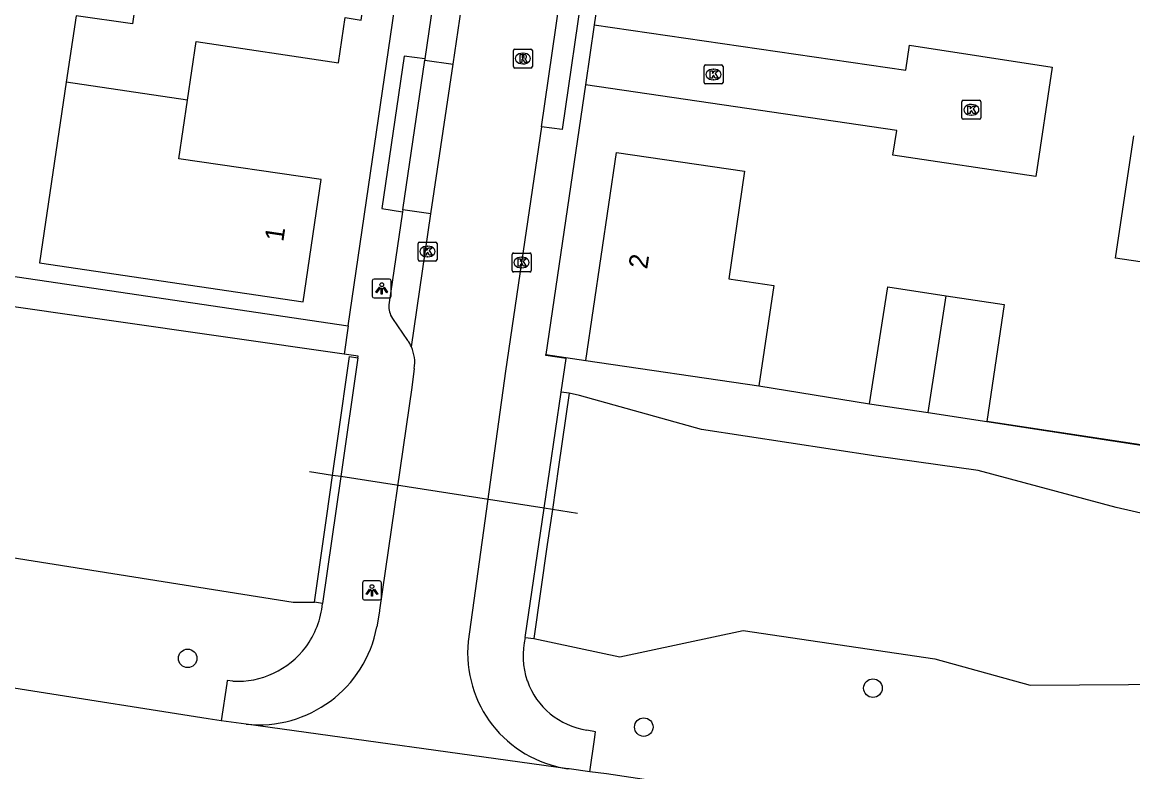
# Model space of a CAD drawing. Extents: x 164150 to 165261, y 382513 to 383432.
# Drawn here: x 164510.6 to 164569.1, y 382845.8 to 382885.3 of the extents above; entities that cross this region are included whole.
import ezdxf

# ---------------------------------------------------------------- set-up
doc = ezdxf.new("R2010")
doc.units = 0
for name, color, linetype in [('IMGEO_Boom', 7, 'Continuous'), ('IMGEO_Duiker', 7, 'Continuous'), ('IMGEO_Greppel_droge_sloot', 7, 'Continuous'), ('IMGEO_Groenvoorziening', 7, 'Continuous'), ('IMGEO_Hek', 7, 'Continuous'), ('IMGEO_Kolk', 7, 'Continuous'), ('IMGEO_Lichtpunt', 7, 'Continuous'), ('IMGEO_Muur', 7, 'Continuous'), ('IMGEO_Pand', 7, 'Continuous'), ('IMGEO_Pand_nummerreeks', 7, 'Continuous'), ('IMGEO_Rijbaan_lokaal_gesloten', 7, 'Continuous'), ('IMGEO_Rijbaan_lokaal_open', 7, 'Continuous'), ('IMGEO_Rioolput', 7, 'Continuous'), ('IMGEO_Voetpad_open', 7, 'Continuous')]:
    doc.layers.add(name, color=color, linetype=linetype)

msp = doc.modelspace()

# ---------------------------------------------------------------- linework, layer by layer
at = {"layer": 'IMGEO_Boom'}
for centre in [(164519.276, 382851.814), (164555.378, 382850.247), (164543.305, 382848.195)]:
    msp.add_circle(centre, 0.489, dxfattribs=at)
at = {"layer": 'IMGEO_Duiker'}
msp.add_lwpolyline([(164539.809, 382859.446), (164538.49, 382859.651), (164538.061, 382859.718), (164527.339, 382861.387), (164526.913, 382861.453), (164525.694, 382861.643)], dxfattribs=at)
at = {"layer": 'IMGEO_Greppel_droge_sloot'}
for points in [[(164527.513, 382867.841), (164483.733, 382874.094), (164468.94, 382876.903), (164467.772, 382876.998)], [(164537.505, 382852.864), (164542.036, 382851.887), (164548.533, 382853.274), (164558.634, 382851.789), (164563.666, 382850.409), (164571.442, 382850.449), (164574.386, 382851.72), (164575.696, 382852.791), (164576.085, 382854.562), (164576.126, 382855.081), (164576.192, 382855.907), (164575.306, 382857.819), (164573.253, 382858.598), (164568.189, 382859.767), (164560.93, 382861.714), (164555.547, 382862.458), (164546.34, 382863.875), (164539.927, 382865.663), (164539.378, 382865.774)], [(164465.924, 382864.054), (164484.051, 382861.245), (164524.835, 382854.782), (164525.957, 382854.773)]]:
    msp.add_lwpolyline(points, dxfattribs=at)
at = {"layer": 'IMGEO_Groenvoorziening'}
for points in [[(164478.67, 382881.048), (164478.137, 382876.668), (164527.73, 382869.322)], [(164538.147, 382867.82), (164540.257, 382867.51)], [(164549.374, 382866.172), (164555.201, 382865.227)], [(164561.373, 382864.283), (164577.746, 382861.779)]]:
    msp.add_lwpolyline(points, dxfattribs=at)
at = {"layer": 'IMGEO_Hek'}
msp.add_lwpolyline([(164578.881, 382869.483), (164577.716, 382861.817), (164561.373, 382864.283)], dxfattribs=at)
at = {"layer": 'IMGEO_Kolk'}
for p, q in [((164546.479, 382882.139), (164546.479, 382882.991)), ((164546.554, 382883.065), (164547.406, 382883.065)), ((164546.967, 382882.845), (164546.992, 382882.845)), ((164547.48, 382882.991), (164547.48, 382882.139)), ((164546.99, 382882.285), (164546.965, 382882.285)), ((164547.406, 382882.065), (164546.554, 382882.065)), ((164560.064, 382880.279), (164560.064, 382881.131)), ((164560.139, 382881.205), (164560.991, 382881.205)), ((164561.065, 382881.131), (164561.065, 382880.279)), ((164560.552, 382880.985), (164560.577, 382880.985)), ((164560.991, 382880.205), (164560.139, 382880.205)), ((164560.575, 382880.425), (164560.55, 382880.425)), ((164531.413, 382872.815), (164531.413, 382873.667)), ((164531.488, 382873.741), (164532.34, 382873.741)), ((164531.901, 382873.521), (164531.926, 382873.521)), ((164532.414, 382873.667), (164532.414, 382872.815)), ((164531.924, 382872.961), (164531.899, 382872.961)), ((164536.367, 382872.237), (164536.367, 382873.089)), ((164536.442, 382873.163), (164537.294, 382873.163)), ((164536.855, 382872.943), (164536.88, 382872.943)), ((164537.368, 382873.089), (164537.368, 382872.237)), ((164532.34, 382872.741), (164531.488, 382872.741)), ((164536.878, 382872.383), (164536.853, 382872.383)), ((164537.294, 382872.163), (164536.442, 382872.163))]:
    msp.add_line(p, q, dxfattribs=at)
for points in [[(164546.479, 382882.139), (164546.479, 382882.991)], [(164546.554, 382883.065), (164547.406, 382883.065)], [(164547.48, 382882.991), (164547.48, 382882.139)], [(164546.8, 382882.765), (164546.923, 382882.765), (164546.923, 382882.614), (164547.053, 382882.765), (164547.217, 382882.765), (164547.071, 382882.614), (164547.224, 382882.365), (164547.072, 382882.365), (164546.987, 382882.529), (164546.923, 382882.462), (164546.923, 382882.365), (164546.8, 382882.365), (164546.8, 382882.765)], [(164547.406, 382882.065), (164546.554, 382882.065)], [(164560.064, 382880.279), (164560.064, 382881.131)], [(164560.139, 382881.205), (164560.991, 382881.205)], [(164561.065, 382881.131), (164561.065, 382880.279)], [(164560.385, 382880.905), (164560.508, 382880.905), (164560.508, 382880.754), (164560.638, 382880.905), (164560.802, 382880.905), (164560.656, 382880.754), (164560.809, 382880.505), (164560.657, 382880.505), (164560.572, 382880.669), (164560.508, 382880.602), (164560.508, 382880.505), (164560.385, 382880.505), (164560.385, 382880.905)], [(164560.991, 382880.205), (164560.139, 382880.205)], [(164531.413, 382872.815), (164531.413, 382873.667)], [(164531.488, 382873.741), (164532.34, 382873.741)], [(164532.414, 382873.667), (164532.414, 382872.815)], [(164531.734, 382873.441), (164531.857, 382873.441), (164531.857, 382873.29), (164531.987, 382873.441), (164532.151, 382873.441), (164532.005, 382873.29), (164532.158, 382873.041), (164532.006, 382873.041), (164531.921, 382873.205), (164531.857, 382873.138), (164531.857, 382873.041), (164531.734, 382873.041), (164531.734, 382873.441)], [(164536.367, 382872.237), (164536.367, 382873.089)], [(164536.442, 382873.163), (164537.294, 382873.163)], [(164537.368, 382873.089), (164537.368, 382872.237)], [(164532.34, 382872.741), (164531.488, 382872.741)], [(164536.688, 382872.863), (164536.811, 382872.863), (164536.811, 382872.712), (164536.941, 382872.863), (164537.105, 382872.863), (164536.959, 382872.712), (164537.112, 382872.463), (164536.96, 382872.463), (164536.875, 382872.627), (164536.811, 382872.56), (164536.811, 382872.463), (164536.688, 382872.463), (164536.688, 382872.863)], [(164537.294, 382872.163), (164536.442, 382872.163)]]:
    msp.add_lwpolyline(points, dxfattribs=at)
for centre, start, end in [((164546.556, 382882.989), 91.55205, 178.44795), ((164546.556, 382882.989), 91.55205, 178.44795), ((164547.404, 382882.989), 1.55205, 88.44795), ((164547.404, 382882.989), 1.55205, 88.44795), ((164546.556, 382882.141), 181.55205, 268.44795), ((164546.556, 382882.141), 181.55205, 268.44795), ((164547.404, 382882.141), 271.55205, 358.44795), ((164547.404, 382882.141), 271.55205, 358.44795), ((164560.141, 382881.129), 91.55205, 178.44795), ((164560.141, 382881.129), 91.55205, 178.44795), ((164560.989, 382881.129), 1.55205, 88.44795), ((164560.989, 382881.129), 1.55205, 88.44795), ((164560.141, 382880.281), 181.55205, 268.44795), ((164560.141, 382880.281), 181.55205, 268.44795), ((164560.989, 382880.281), 271.55205, 358.44795), ((164560.989, 382880.281), 271.55205, 358.44795), ((164531.49, 382873.665), 91.55205, 178.44795), ((164531.49, 382873.665), 91.55205, 178.44795), ((164532.338, 382873.665), 1.55205, 88.44795), ((164532.338, 382873.665), 1.55205, 88.44795), ((164536.444, 382873.087), 91.55205, 178.44795), ((164536.444, 382873.087), 91.55205, 178.44795), ((164537.292, 382873.087), 1.55205, 88.44795), ((164537.292, 382873.087), 1.55205, 88.44795), ((164531.49, 382872.817), 181.55205, 268.44795), ((164531.49, 382872.817), 181.55205, 268.44795), ((164532.338, 382872.817), 271.55205, 358.44795), ((164532.338, 382872.817), 271.55205, 358.44795), ((164536.444, 382872.239), 181.55205, 268.44795), ((164536.444, 382872.239), 181.55205, 268.44795), ((164537.292, 382872.239), 271.55205, 358.44795), ((164537.292, 382872.239), 271.55205, 358.44795)]:
    msp.add_arc(centre, 0.0765, start, end, dxfattribs=at)
for centre, major_axis, ratio, start_param, end_param in [((164546.966, 382882.565), (-0.387, 0.002), 0.722429, 4.712389, 7.853982), ((164546.991, 382882.565), (-0.39, 0.002), 0.717154, 1.570796, 4.712389), ((164560.551, 382880.705), (-0.387, 0.002), 0.722429, 4.712389, 7.853982), ((164560.576, 382880.705), (-0.39, 0.002), 0.717154, 1.570796, 4.712389), ((164531.9, 382873.241), (-0.387, 0.002), 0.722429, 4.712389, 7.853982), ((164531.925, 382873.241), (-0.39, 0.002), 0.717154, 1.570796, 4.712389), ((164536.854, 382872.663), (-0.387, 0.002), 0.722429, 4.712389, 7.853982), ((164536.879, 382872.663), (-0.39, 0.002), 0.717154, 1.570796, 4.712389)]:
    msp.add_ellipse(centre, major_axis=major_axis, ratio=ratio, start_param=start_param, end_param=end_param, dxfattribs=at)
at = {"layer": 'IMGEO_Lichtpunt'}
for p, q in [((164529.903, 382871.791), (164529.095, 382871.791)), ((164529.903, 382871.791), (164529.095, 382871.791)), ((164529.001, 382871.696), (164529.001, 382870.889)), ((164529.001, 382871.696), (164529.001, 382870.889)), ((164529.997, 382870.889), (164529.997, 382871.696)), ((164529.997, 382870.889), (164529.997, 382871.696)), ((164529.095, 382870.795), (164529.903, 382870.795)), ((164529.095, 382870.795), (164529.903, 382870.795)), ((164528.487, 382855.797), (164528.487, 382854.99)), ((164528.487, 382855.797), (164528.487, 382854.99)), ((164529.389, 382855.892), (164528.581, 382855.892)), ((164529.389, 382855.892), (164528.581, 382855.892)), ((164529.483, 382854.99), (164529.483, 382855.797)), ((164529.483, 382854.99), (164529.483, 382855.797)), ((164528.581, 382854.896), (164529.389, 382854.896)), ((164528.581, 382854.896), (164529.389, 382854.896))]:
    msp.add_line(p, q, dxfattribs=at)
for points in [[(164529.375, 382871.36), (164529.414, 382871.332), (164529.226, 382871.07), (164529.188, 382871.097), (164529.375, 382871.36)], [(164529.477, 382871.312), (164529.524, 382871.312), (164529.524, 382870.99), (164529.477, 382870.99), (164529.477, 382871.312)], [(164529.587, 382871.332), (164529.625, 382871.359), (164529.812, 382871.097), (164529.773, 382871.069), (164529.587, 382871.332)], [(164528.861, 382855.461), (164528.9, 382855.433), (164528.712, 382855.171), (164528.674, 382855.198), (164528.861, 382855.461)], [(164528.963, 382855.413), (164529.01, 382855.413), (164529.01, 382855.091), (164528.963, 382855.091), (164528.963, 382855.413)], [(164529.073, 382855.433), (164529.111, 382855.46), (164529.298, 382855.198), (164529.259, 382855.17), (164529.073, 382855.433)]]:
    msp.add_lwpolyline(points, dxfattribs=at)
for centre in [(164529.5, 382871.494), (164528.986, 382855.595)]:
    msp.add_circle(centre, 0.0994, dxfattribs=at)
for centre, start, end in [((164529.095, 382871.696), 90, 180), ((164529.095, 382871.696), 90, 180), ((164529.903, 382871.696), 0, 90), ((164529.903, 382871.696), 0, 90), ((164529.095, 382870.889), 180, 270), ((164529.095, 382870.889), 180, 270), ((164529.903, 382870.889), 270, 0), ((164529.903, 382870.889), 270, 360), ((164528.581, 382855.797), 90, 180), ((164528.581, 382855.797), 90, 180), ((164529.389, 382855.797), 0, 90), ((164529.389, 382855.797), 0, 90), ((164528.581, 382854.99), 180, 270), ((164528.581, 382854.99), 180, 270), ((164529.389, 382854.99), 270, 0), ((164529.389, 382854.99), 270, 360)]:
    msp.add_arc(centre, 0.0946, start, end, dxfattribs=at)
at = {"layer": 'IMGEO_Muur'}
for points in [[(164525.957, 382854.773), (164526.609, 382859.328), (164526.913, 382861.453), (164527.19, 382863.393), (164527.808, 382867.71), (164528.242, 382867.643)], [(164528.242, 382867.643), (164527.339, 382861.387), (164526.374, 382854.707)], [(164537.064, 382852.92), (164538.061, 382859.718), (164538.958, 382865.839)], [(164539.378, 382865.774), (164538.817, 382861.909), (164538.49, 382859.651), (164538.224, 382857.818), (164537.505, 382852.864)], [(164539.378, 382865.774), (164538.958, 382865.839)], [(164526.374, 382854.707), (164525.957, 382854.773)], [(164537.064, 382852.92), (164537.505, 382852.864)]]:
    msp.add_lwpolyline(points, dxfattribs=at)
at = {"layer": 'IMGEO_Pand'}
for points in [[(164517.196, 382890.97), (164516.368, 382885.227), (164513.394, 382885.655), (164512.877, 382882.156)], [(164519.273, 382881.212), (164519.728, 382884.295), (164527.229, 382883.186), (164527.578, 382885.569), (164528.423, 382885.433), (164528.982, 382889.238)], [(164512.877, 382882.156), (164511.47, 382872.646), (164525.363, 382870.591), (164526.315, 382877.031), (164518.818, 382878.129), (164519.273, 382881.212)], [(164519.273, 382881.212), (164512.877, 382882.156)], [(164578.881, 382869.483), (164573.443, 382870.291), (164573.707, 382872.068), (164568.164, 382872.891), (164569.122, 382879.34)], [(164540.257, 382867.51), (164541.862, 382878.449), (164548.607, 382877.475), (164547.781, 382871.803), (164550.149, 382871.456), (164549.374, 382866.172)], [(164555.201, 382865.227), (164556.155, 382871.378), (164559.229, 382870.911)], [(164558.287, 382864.755), (164559.229, 382870.911)], [(164559.229, 382870.911), (164562.299, 382870.444), (164561.373, 382864.283)], [(164540.257, 382867.51), (164549.374, 382866.172)], [(164555.201, 382865.227), (164558.287, 382864.755)], [(164558.287, 382864.755), (164561.373, 382864.283)]]:
    msp.add_lwpolyline(points, dxfattribs=at)
at = {"layer": 'IMGEO_Rijbaan_lokaal_gesloten'}
for points in [[(164521.046, 382848.53), (164520.361, 382848.623), (164501.188, 382851.646), (164471.939, 382855.982), (164471.335, 382856.066)], [(164522.349, 382848.352), (164521.046, 382848.53)], [(164539.309, 382846.004), (164522.349, 382848.352)], [(164540.462, 382845.846), (164539.367, 382845.996), (164539.338, 382846), (164539.309, 382846.004)], [(164577.371, 382840.307), (164541.34, 382845.725), (164540.462, 382845.846)]]:
    msp.add_lwpolyline(points, dxfattribs=at)
at = {"layer": 'IMGEO_Rijbaan_lokaal_open'}
for points in [[(164533.255, 382883.11), (164534.839, 382893.869)], [(164537.91, 382879.804), (164539.063, 382887.71)], [(164540.7, 382885.173), (164557.112, 382882.794), (164557.31, 382884.103), (164564.82, 382882.958), (164563.954, 382877.188), (164556.429, 382878.318), (164556.635, 382879.621), (164540.236, 382882.018)], [(164540.7, 382885.173), (164540.236, 382882.018)], [(164532.094, 382875.226), (164533.255, 382883.11)], [(164537.91, 382879.804), (164536.868, 382872.663), (164536.025, 382866.945), (164534.057, 382852.71)], [(164531.063, 382868.222), (164532.094, 382875.226)], [(164531.215, 382867.083), (164531.078, 382866.085), (164529.388, 382854.359), (164529.379, 382854.301), (164529.244, 382853.47)]]:
    msp.add_lwpolyline(points, dxfattribs=at)
for centre, radius, start, end in [((164529.284, 382867.405), 1.957, 350.53101, 24.67146), ((164523.019, 382854.652), 6.336, 263.92546, 349.24583), ((164540.182, 382852.098), 6.156, 174.29042, 261.8442)]:
    msp.add_arc(centre, radius, start, end, dxfattribs=at)
at = {"layer": 'IMGEO_Rioolput'}
for p, q in [((164536.435, 382882.979), (164536.435, 382883.831)), ((164536.51, 382883.905), (164537.362, 382883.905)), ((164536.923, 382883.685), (164536.948, 382883.685)), ((164537.436, 382883.831), (164537.436, 382882.979)), ((164537.362, 382882.905), (164536.51, 382882.905)), ((164536.946, 382883.125), (164536.921, 382883.125))]:
    msp.add_line(p, q, dxfattribs=at)
for points in [[(164536.435, 382882.979), (164536.435, 382883.831)], [(164536.51, 382883.905), (164537.362, 382883.905)], [(164537.024, 382883.603), (164536.772, 382883.605), (164536.772, 382883.205)], [(164536.95, 382883.524), (164536.896, 382883.524), (164536.896, 382883.443)], [(164536.896, 382883.443), (164536.948, 382883.443)], [(164537.436, 382883.831), (164537.436, 382882.979)], [(164537.362, 382882.905), (164536.51, 382882.905)], [(164536.772, 382883.205), (164536.896, 382883.205), (164536.896, 382883.367), (164536.907, 382883.367)], [(164536.954, 382883.338), (164537.025, 382883.205), (164537.165, 382883.205), (164537.1, 382883.331)]]:
    msp.add_lwpolyline(points, dxfattribs=at)
for centre, radius, start, end in [((164536.512, 382883.829), 0.0765, 91.55205, 178.44795), ((164536.512, 382883.829), 0.0765, 91.55205, 178.44795), ((164536.932, 382883.632), 0.19, 274.7715, 282.96867), ((164536.956, 382883.428), 0.0964, 77.00612, 93.18647), ((164536.97, 382883.485), 0.0378, 276.66336, 79.67722), ((164537.023, 382883.493), 0.109, 350.36119, 89.41601), ((164537.021, 382883.493), 0.112, 277.58423, 350.98172), ((164537.36, 382883.829), 0.0765, 1.55205, 88.44795), ((164537.36, 382883.829), 0.0765, 1.55205, 88.44795), ((164536.512, 382882.981), 0.0765, 181.55205, 268.44795), ((164536.512, 382882.981), 0.0765, 181.55205, 268.44795), ((164536.906, 382883.314), 0.0533, 26.02933, 88.69889), ((164537.005, 382883.278), 0.108, 29.51342, 73.79051), ((164537.36, 382882.981), 0.0765, 271.55205, 358.44795), ((164537.36, 382882.981), 0.0765, 271.55205, 358.44795)]:
    msp.add_arc(centre, radius, start, end, dxfattribs=at)
for centre, major_axis, ratio, start_param, end_param in [((164536.922, 382883.405), (-0.387, 0.002), 0.722429, 4.712389, 7.853982), ((164536.947, 382883.405), (-0.39, 0.002), 0.717154, 1.570796, 4.712389)]:
    msp.add_ellipse(centre, major_axis=major_axis, ratio=ratio, start_param=start_param, end_param=end_param, dxfattribs=at)
at = {"layer": 'IMGEO_Voetpad_open'}
for points in [[(164527.73, 382869.322), (164536.67, 382930.425), (164544.133, 382980.726), (164542.913, 382982.243), (164519.298, 382985.737), (164495.986, 382989.176)], [(164544.373, 382910.128), (164540.7, 382885.173)], [(164533.317, 382893.95), (164531.771, 382883.381)], [(164539.063, 382887.71), (164540.151, 382887.546), (164539.003, 382879.661), (164537.91, 382879.804)], [(164531.771, 382883.381), (164530.69, 382883.53), (164529.503, 382875.504), (164530.594, 382875.339)], [(164530.609, 382875.44), (164531.762, 382883.32)], [(164531.771, 382883.381), (164531.762, 382883.32)], [(164531.762, 382883.32), (164533.255, 382883.11)], [(164540.236, 382882.018), (164538.147, 382867.82)], [(164530.594, 382875.339), (164529.877, 382870.437)], [(164530.609, 382875.44), (164530.594, 382875.339)], [(164532.094, 382875.226), (164530.609, 382875.44)], [(164530.061, 382869.713), (164530.863, 382868.563)], [(164527.73, 382869.322), (164527.513, 382867.841)], [(164528.242, 382867.643), (164528.255, 382867.732), (164527.513, 382867.841)], [(164538.958, 382865.839), (164539.217, 382867.609), (164538.138, 382867.763), (164538.147, 382867.82)], [(164521.649, 382850.615), (164521.357, 382850.657), (164521.333, 382850.492), (164521.046, 382848.53)], [(164540.462, 382845.846), (164540.704, 382847.546), (164540.762, 382847.952), (164540.302, 382848.037)]]:
    msp.add_lwpolyline(points, dxfattribs=at)
for centre, radius, start, end in [((164531.014, 382870.341), 1.141, 175.14797, 213.37097), ((164529.289, 382867.411), 1.951, 24.57653, 36.20759), ((164521.886, 382855.108), 4.506, 323.19983, 354.89232), ((164521.895, 382855.105), 4.497, 266.8627, 323.16293), ((164540.897, 382851.948), 3.955, 165.77544, 199.51809), ((164540.895, 382851.943), 3.95, 199.45212, 261.36995)]:
    msp.add_arc(centre, radius, start, end, dxfattribs=at)

# ---------------------------------------------------------------- texts
at = {"layer": 'IMGEO_Pand_nummerreeks'}
for s, rotation, p in [('1', 81.58919, (164524.311, 382873.73)), ('2', 81.65222, (164543.484, 382872.286))]:
    msp.add_text(s, height=1, rotation=rotation, dxfattribs=at).set_placement(p)

doc.saveas('drawing.dxf')
